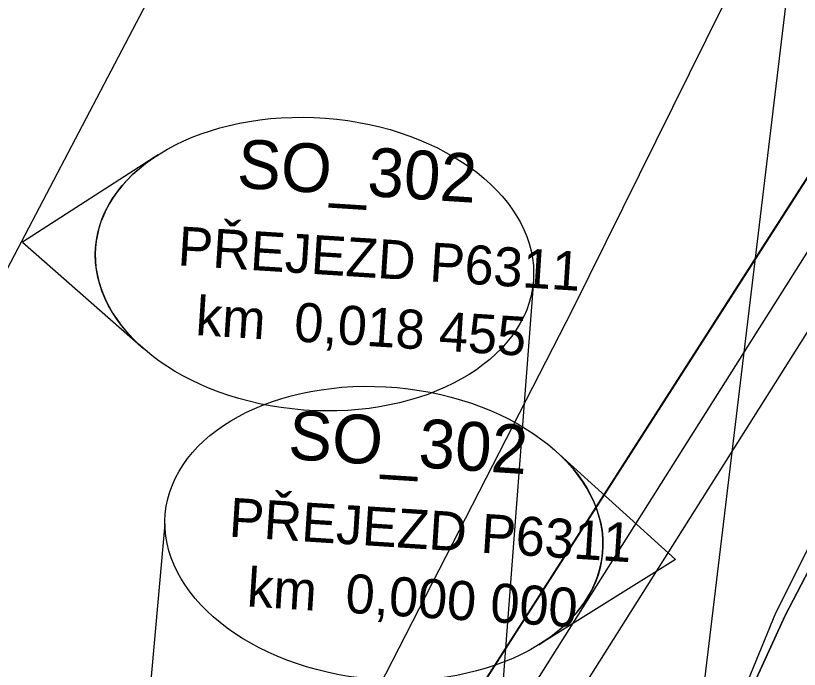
# Model space of a CAD drawing. Extents: x -746176 to -739709, y -1128407 to -1124482.
# Drawn here: x -743187.21 to -743147.05, y -1127071.55 to -1127038.05 of the extents above; entities that cross this region are included whole.
import ezdxf

# ---------------------------------------------------------------- set-up
doc = ezdxf.new("R2010")
doc.units = 0
for name, color, linetype in [('_Násyp', 7, 'Continuous'), ('_TRASA_vedení kabelu_CEZ', 7, 'Continuous'), ('_Zabezpečovací zařízení_trasa', 7, 'Continuous'), ('bublina_fialová_čára_tenká', 7, 'Continuous'), ('bublina_růžová_230_čára_tučná', 7, 'Continuous'), ('Hranice parcel', 7, 'Continuous'), ('SMER_VYS_VYROVNANI', 7, 'Continuous'), ('Vrstva 53', 7, 'Continuous')]:
    doc.layers.add(name, color=color, linetype=linetype)

msp = doc.modelspace()

# ---------------------------------------------------------------- linework, layer by layer
at = {"layer": '_TRASA_vedení kabelu_CEZ'}
msp.add_lwpolyline([(-743153.07, -1127080.408), (-743148.258, -1127068.653), (-743137.261, -1127046.755), (-743132.067, -1127038.676)], dxfattribs=at)
at = {"layer": '_Zabezpečovací zařízení_trasa'}
msp.add_lwpolyline([(-743018.819, -1126847.736), (-743049.28, -1126895.951), (-743072.487, -1126932.751), (-743098.647, -1126974.146), (-743125.94, -1127017.384), (-743152.604, -1127059.608), (-743175.023, -1127095.116), (-743199.163, -1127133.346), (-743215.971, -1127159.941), (-743232.818, -1127186.515), (-743247.456, -1127209.811), (-743254.52, -1127221.639), (-743261.299, -1127233.691), (-743264.155, -1127239.195), (-743264.862, -1127241.108), (-743267.337, -1127245.816), (-743268.289, -1127247.159), (-743271.711, -1127253.75), (-743281.122, -1127274.196), (-743291.923, -1127301.42), (-743296.724, -1127315.222), (-743301.116, -1127329.128), (-743306.787, -1127349.506)], dxfattribs=at)
at = {"layer": 'bublina_fialová_čára_tenká'}
for p, q in [((-743145.088, -1127015.481), (-743152.928, -1127080.479)), ((-743160.679, -1127051.634), (-743164.286, -1127099.423)), ((-743179.562, -1127064.096), (-743182.5, -1127096.45))]:
    msp.add_line(p, q, dxfattribs=at)
at = {"layer": 'bublina_růžová_230_čára_tučná'}
for p, q in [((-743179.913, -1127045.19), (-743186.854, -1127049.658)), ((-743179.913, -1127045.19), (-743186.854, -1127049.658)), ((-743186.854, -1127049.658), (-743180.663, -1127055.117)), ((-743186.854, -1127049.658), (-743180.663, -1127055.117)), ((-743159.51, -1127060.384), (-743153.397, -1127065.932)), ((-743159.51, -1127060.384), (-743153.397, -1127065.932)), ((-743153.397, -1127065.932), (-743160.402, -1127070.299)), ((-743153.397, -1127065.932), (-743160.402, -1127070.299))]:
    msp.add_line(p, q, dxfattribs=at)
for centre, major_axis in [((-743171.897, -1127050.787), (11.218, -0.847)), ((-743168.337, -1127064.588), (-11.205, 1.008))]:
    msp.add_ellipse(centre, major_axis=major_axis, ratio=0.666667, dxfattribs=at)
for centre, major_axis in [((-743171.897, -1127050.787), (-11.22, 0.847)), ((-743168.337, -1127064.588), (11.206, -1.008))]:
    msp.add_ellipse(centre, major_axis=major_axis, ratio=0.666473, start_param=5.557317, end_param=7.009053, dxfattribs=at)
at = {"layer": 'Hranice parcel'}
for points in [[(-743206.78, -1127087.5), (-743159.7, -1126997.73), (-743124.42, -1126927.65)], [(-743178.51, -1127091.81), (-743158.66, -1127053.1), (-743097.21, -1126928.95)], [(-743080.97, -1126930.41), (-743108.67, -1126985.4), (-743124.8, -1127012.28), (-743175.35, -1127091.16), (-743178.51, -1127091.81)], [(-743159.64, -1127094.74), (-743147.78, -1127068.8), (-743136.47, -1127047.12), (-743093.1, -1126978.92), (-743082.27, -1126962.07)]]:
    msp.add_lwpolyline(points, dxfattribs=at)
at = {"layer": 'SMER_VYS_VYROVNANI'}
msp.add_lwpolyline([(-743143.427, -1127049.192), (-743169.53, -1127090.542)], dxfattribs=at)
at = {"layer": 'Vrstva 53'}
msp.add_lwpolyline([(-743032.8, -1126884.17), (-743063.8, -1126932.98), (-743082.27, -1126962.07), (-743093.1, -1126978.92), (-743136.47, -1127047.12), (-743147.78, -1127068.8), (-743159.64, -1127094.74), (-743160.17, -1127095.91), (-743166.78, -1127095.57), (-743176.42, -1127093.47), (-743180.17, -1127093.19), (-743180.08, -1127092.14), (-743178.51, -1127091.81), (-743175.35, -1127091.16), (-743150.075, -1127051.72), (-743124.8, -1127012.28), (-743108.67, -1126985.4), (-743080.97, -1126930.41), (-743079.79, -1126928.05), (-743048.51, -1126865.51), (-743045.12, -1126860.39), (-743029.24, -1126857.99)], dxfattribs=at)

# ---------------------------------------------------------------- texts
at = {"layer": '_Násyp'}
for s, height, p in [('SO_302', 2.5, (-743175.908, -1127046.867)), ('PŘEJEZD P6311', 2, (-743178.937, -1127050.846)), ('km  0,018 455', 2, (-743178.022, -1127054.419)), ('SO_302', 2.5, (-743173.286, -1127060.774)), ('PŘEJEZD P6311', 2, (-743176.314, -1127064.752)), ('km  0,000 000', 2, (-743175.393, -1127068.327))]:
    msp.add_text(s, height=height, rotation=356.3528, dxfattribs=at).set_placement(p)

doc.saveas('drawing.dxf')
